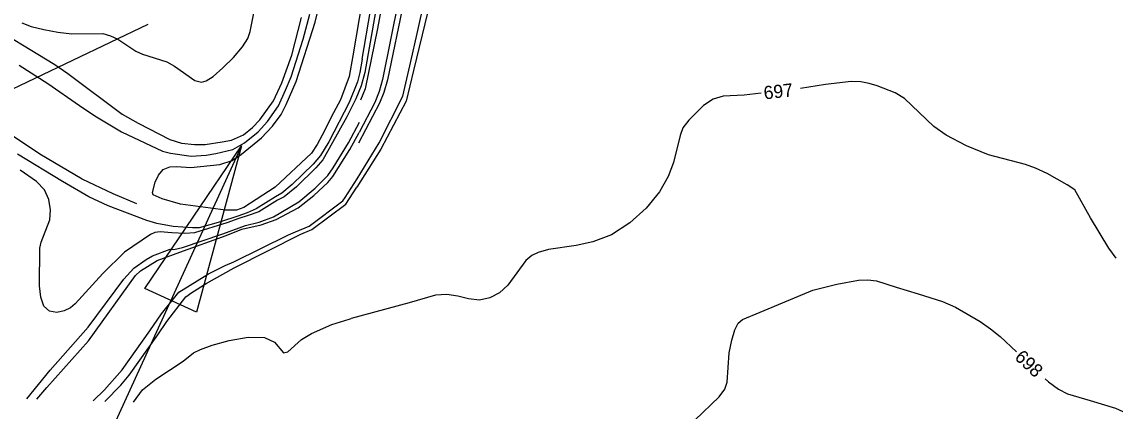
# Model space of a CAD drawing. Extents: x -291892836 to 2945206, y -477993085 to 1832792.
# Drawn here: x 1850501.2 to 1850832.6, y 543573.1 to 543691.2 of the extents above; entities that cross this region are included whole.
import ezdxf

# ---------------------------------------------------------------- set-up
doc = ezdxf.new("R2010")
doc.units = 0
for name, color, linetype in [('DT_X_Contour_Minor', 7, 'Continuous'), ('Level 19', 7, 'Continuous'), ('Level 40', 7, 'Continuous')]:
    doc.layers.add(name, color=color, linetype=linetype)

msp = doc.modelspace()

# ---------------------------------------------------------------- linework, layer by layer
at = {"layer": 'DT_X_Contour_Minor'}
for points in [[(1850602.8, 543643.63), (1850609.51, 543654.48), (1850616.7, 543668.65), (1850619.07, 543679.23), (1850621, 543687.7), (1850623.33, 543698.2), (1850623.59, 543708.05), (1850623.55, 543715.12), (1850621.4, 543727.85), (1850620.21, 543734.29), (1850614.27, 543761.79), (1850613.42, 543765), (1850613.12, 543767.45), (1850613.42, 543769.67)], [(1850607.92, 543765.92), (1850610.49, 543756.28), (1850612.11, 543749.43), (1850614.05, 543742.27), (1850616.01, 543732.6), (1850618.19, 543715.1), (1850617.77, 543703.74), (1850616.93, 543697.52), (1850611.97, 543673.63), (1850610.95, 543669.76), (1850609.57, 543666.53), (1850603.25, 543654.4)], [(1850607.76, 543762.07), (1850609.26, 543756.26), (1850610.91, 543749.6), (1850612.92, 543742.42), (1850614.51, 543734.76), (1850616.32, 543721.99), (1850616.8, 543717.39), (1850616.72, 543710.8), (1850616.36, 543704.55), (1850615.39, 543697.78), (1850610.52, 543673.75), (1850609.51, 543670.04), (1850608.14, 543666.78), (1850603.38, 543657.64)], [(1850607.27, 543750.19), (1850610.01, 543740.77), (1850611.18, 543733.88), (1850612.69, 543720.84), (1850612.67, 543714.51), (1850612.45, 543710.06), (1850611.51, 543702.93), (1850608.95, 543689.24), (1850605.2, 543670.87), (1850603.79, 543667.44)], [(1850607.14, 543747.12), (1850608.83, 543741.15), (1850609.98, 543734.21), (1850611.24, 543723.1), (1850611.4, 543719.2), (1850611.07, 543710.81), (1850610.03, 543703.52), (1850605.11, 543675.86), (1850603.98, 543671.77)], [(1850604.32, 543679.91), (1850606.89, 543694.64), (1850609.69, 543711.57), (1850610, 543717.37), (1850609.97, 543723.38), (1850608.37, 543737.27), (1850607.26, 543743.17), (1850607.01, 543744.02)], [(1850605.31, 543703.64), (1850601.48, 543680.89), (1850600.41, 543674.59), (1850597.72, 543667.58), (1850595.62, 543663.59), (1850592.19, 543656.79), (1850590.72, 543653.96), (1850588.97, 543651.4)], [(1850501.14, 543690.87), (1850504.01, 543689.85), (1850507.81, 543688.85), (1850512.08, 543688.04), (1850516.26, 543687.59), (1850525.69, 543687.65), (1850528.08, 543687), (1850530.23, 543685.93), (1850535.72, 543682.33), (1850537.71, 543681.4), (1850545.08, 543679.04), (1850547.42, 543677.72), (1850553.61, 543673.4), (1850555.59, 543672.92), (1850556.99, 543673.31), (1850559.11, 543674.67), (1850562.1, 543677.22), (1850565.36, 543680.43), (1850568.07, 543683.6), (1850569.65, 543686.17), (1850570.37, 543688.31), (1850571.65, 543694.82)], [(1850588.97, 543651.4), (1850577.98, 543641.01), (1850568.5, 543634.86), (1850566.26, 543634.06), (1850562.86, 543634.12), (1850549.22, 543635.9), (1850543.71, 543637.53), (1850540.97, 543638.69), (1850540.74, 543639.39), (1850541.62, 543642.56), (1850542.59, 543644.71), (1850544.04, 543646.41), (1850545.98, 543647.19), (1850548.02, 543647.28), (1850552.37, 543646.98), (1850561.21, 543647.98), (1850564.9, 543649.17), (1850567.73, 543651.02), (1850573.86, 543655.99), (1850577.14, 543659.53), (1850579.75, 543663.07), (1850581.34, 543666.11), (1850584.32, 543673.14), (1850590.11, 543691.16), (1850591.38, 543696.58)], [(1850624.2, 543694.36), (1850619.94, 543676.45), (1850617.66, 543667.1), (1850610.04, 543652.55), (1850602.69, 543641.03)], [(1850489.09, 543691.62), (1850511.12, 543678.26), (1850515.13, 543675.56), (1850531.61, 543663.2), (1850536.44, 543660.49), (1850545.97, 543655.54), (1850549.6, 543654.45), (1850553.48, 543653.98), (1850556.78, 543654.04), (1850561.91, 543654.8), (1850564.75, 543655.35), (1850568.32, 543656.92), (1850571.07, 543659.17), (1850573.33, 543661.48), (1850577.5, 543667.24), (1850579.99, 543672.75), (1850582.98, 543681.15), (1850585.95, 543692.58)], [(1850500.3, 543678.11), (1850509.07, 543672.56), (1850518.64, 543665.79), (1850523.3, 543662.72), (1850531.39, 543657.86), (1850543.79, 543651.99), (1850546.26, 543651.32), (1850552.45, 543650.45), (1850556.99, 543650.73), (1850559.97, 543651.22), (1850565.11, 543652.44), (1850568.7, 543654.5), (1850572.78, 543657.86), (1850575.58, 543660.94), (1850578.96, 543665.72), (1850581.13, 543670.44), (1850582.78, 543674.58), (1850586.45, 543685.95), (1850588.45, 543693.55)], [(1850604.32, 543679.91), (1850603.62, 543675.8), (1850602.89, 543673.02), (1850600.39, 543666.74), (1850594.23, 543654.77), (1850591.68, 543650.67), (1850589.43, 543648.04), (1850583.14, 543641.87), (1850579.94, 543639.23), (1850578.08, 543638.13), (1850572.22, 543634.43), (1850569.46, 543633.27), (1850566.6, 543632.29), (1850561.35, 543630.56), (1850554.89, 543628.74), (1850552.92, 543628.68), (1850547.03, 543629.13), (1850542.08, 543630.01), (1850539.08, 543630.91), (1850527.32, 543635.43), (1850521.48, 543638.11), (1850513.43, 543642.81), (1850499.87, 543651.05)], [(1850603.98, 543671.77), (1850602.41, 543667.81), (1850599.66, 543662.35), (1850592.43, 543649.39), (1850590.33, 543646.93), (1850584.44, 543641.19), (1850580.66, 543638.17), (1850578.69, 543637.06), (1850573.02, 543633.61), (1850569.79, 543632.41), (1850566.96, 543631.56), (1850563.35, 543630.2), (1850553.53, 543627.24), (1850550.53, 543626.98), (1850546.65, 543627.15), (1850543.04, 543627.45), (1850541.49, 543627.28), (1850540.15, 543626.72), (1850532.32, 543621.31), (1850525.66, 543614.82), (1850517.33, 543605.66), (1850515.86, 543604.48), (1850513.97, 543603.51), (1850511.74, 543603.05), (1850509.54, 543603.41), (1850507.81, 543604.93), (1850506.86, 543607.72), (1850506.51, 543611.11), (1850506.58, 543622.53), (1850506.98, 543624.35), (1850509.62, 543631.19), (1850509.87, 543634.16), (1850509.38, 543637.27), (1850507.97, 543640.22), (1850505.63, 543642.76), (1850500.66, 543646.19)], [(1850832.89, 543619.53), (1850830.66, 543622.51), (1850825.14, 543631.73), (1850820.39, 543640.24), (1850818.08, 543641.75), (1850812, 543645.17), (1850808.52, 543646.81), (1850805.4, 543647.92), (1850794.19, 543650.88), (1850787.58, 543653.63), (1850781.39, 543656.84), (1850777.7, 543659.42), (1850768.77, 543667.97), (1850765.93, 543669.67), (1850760.47, 543671.8), (1850758.06, 543672.54), (1850755.56, 543673.03), (1850752.6, 543673.13), (1850744.78, 543672.16), (1850737.22, 543671.03)], [(1850725.32, 543669.54), (1850720.11, 543668.95), (1850713.77, 543668.64), (1850710.74, 543667.71), (1850707.86, 543665.83), (1850703.38, 543661.38), (1850701.52, 543659.07), (1850700.74, 543656.77), (1850698.72, 543648.52), (1850697.14, 543644.3), (1850694.48, 543639.61), (1850690.48, 543634.72), (1850685.46, 543630.19), (1850679.9, 543626.62), (1850674.3, 543624.44), (1850669.19, 543623.35), (1850660.81, 543622.18), (1850657.68, 543621.23), (1850655.78, 543620.3), (1850653.92, 543618.78), (1850648.48, 543611.27), (1850645.97, 543609.02), (1850643.05, 543607.44), (1850639.88, 543606.79), (1850636.62, 543607.15), (1850633.32, 543607.96), (1850629.99, 543608.51), (1850626.6, 543608.26), (1850618.55, 543605.97), (1850601.02, 543601.19)], [(1850536.05, 543636), (1850528.8, 543638.98), (1850519.43, 543643.5), (1850506.65, 543651.11), (1850488.56, 543663.07)], [(1850502.7, 543576.8), (1850509.72, 543585.56), (1850521.23, 543598.54), (1850532.05, 543613.13), (1850535.13, 543616.44), (1850538.85, 543619.11), (1850540.81, 543620.17), (1850546.17, 543622.22), (1850547.26, 543622.15), (1850549.84, 543622.72), (1850562.08, 543626.86), (1850568.95, 543629.46), (1850573.07, 543630.42), (1850577.47, 543632.09), (1850585.14, 543636.59), (1850590.11, 543640.73), (1850593.94, 543644.6), (1850595.53, 543646.89), (1850600.21, 543654.48), (1850603.52, 543660.81)], [(1850505.7, 543576.71), (1850508.74, 543580.3), (1850521.34, 543594.38), (1850535.6, 543614.3), (1850537.14, 543615.68), (1850542.13, 543618.79), (1850549.06, 543621.28), (1850563.12, 543626.38), (1850567.88, 543628.34), (1850573.68, 543629.6), (1850578.28, 543631.2), (1850584.93, 543634.82), (1850589.66, 543638.49), (1850593.93, 543642.48), (1850595.41, 543644.3), (1850600.62, 543652.51), (1850603.38, 543657.64)], [(1850522.75, 543576.18), (1850526.17, 543579.58), (1850531.52, 543585.61), (1850539.97, 543597.41), (1850543.49, 543602.64), (1850548.74, 543609.17), (1850557.77, 543614.71), (1850562.84, 543617.27), (1850565.41, 543618.37), (1850582.04, 543626.57), (1850584.16, 543627.46), (1850588.27, 543629.25), (1850598.44, 543636.92), (1850599.15, 543637.94), (1850602.8, 543643.63)], [(1850526.35, 543576.06), (1850531.2, 543580.99), (1850533.65, 543584.01), (1850542.42, 543596.25), (1850545.06, 543600.27), (1850550.9, 543607.77), (1850552.66, 543609.14), (1850557, 543611.83), (1850565.56, 543616.62), (1850585.74, 543626.77), (1850589.08, 543628.24), (1850599.42, 543635.93), (1850602.69, 543641.03)], [(1850705.2, 543570.38), (1850712.61, 543577.45), (1850714.27, 543579.71), (1850714.96, 543581.84), (1850715.6, 543590.77), (1850716.39, 543594.61), (1850717.33, 543597.79), (1850718.31, 543599.75), (1850719.66, 543600.89), (1850724.97, 543603.15), (1850741.01, 543609.75), (1850748.2, 543611.6), (1850754.84, 543612.79), (1850757.6, 543612.94), (1850760.31, 543612.64), (1850766.26, 543610.76), (1850772.93, 543608.69), (1850780.31, 543606.41), (1850784.26, 543604.61), (1850791.74, 543600.26), (1850794.85, 543598.11), (1850797.8, 543595.77), (1850802.73, 543591.12)], [(1850535.05, 543575.79), (1850537.7, 543579.58), (1850541.81, 543582.77), (1850550.08, 543588.25), (1850553.23, 543590.74), (1850555.32, 543591.8), (1850558.83, 543593.08), (1850564.02, 543594.51), (1850569.79, 543595.53), (1850574.71, 543595.48), (1850577.75, 543594), (1850580.48, 543590.74), (1850581.78, 543591.12), (1850585.93, 543594.78), (1850588.96, 543596.66), (1850595.1, 543599.35), (1850600.44, 543601.03), (1850601.02, 543601.19)], [(1850811.45, 543582.87), (1850812.41, 543581.96), (1850815.43, 543579.73), (1850818.2, 543578.34), (1850825.03, 543576.31), (1850832.75, 543573.98), (1850840.54, 543570.46), (1850843.22, 543569.82), (1850846.2, 543569.48), (1850852.85, 543569.43), (1850863.48, 543570.02), (1850866.5, 543569.72), (1850868.56, 543568.43), (1850869.3, 543565.86), (1850869.19, 543565.1)]]:
    msp.add_lwpolyline(points, dxfattribs=at)
at = {"layer": 'Level 40'}
for p, q in [((1850007.65, 543436.21), (1850539.4, 543690.48)), ((1850538.47, 543610.28), (1850567.72, 543653.62)), ((1850567.72, 543653.62), (1850554.09, 543603.14)), ((1850554.09, 543603.14), (1850538.47, 543610.28))]:
    msp.add_line(p, q, dxfattribs=at)
msp.add_lwpolyline([(1850567.72, 543653.62), (1850450.55, 543397.08), (1850418.67, 543366.99)], dxfattribs=at)

# ---------------------------------------------------------------- texts
at = {"layer": 'Level 19'}
for s, rotation, p in [('697', 6.4859, (1850726.28, 543667.64)), ('698', 316.5649, (1850801.91, 543589.15))]:
    msp.add_text(s, height=4, rotation=rotation, dxfattribs=at).set_placement(p)

doc.saveas('drawing.dxf')
